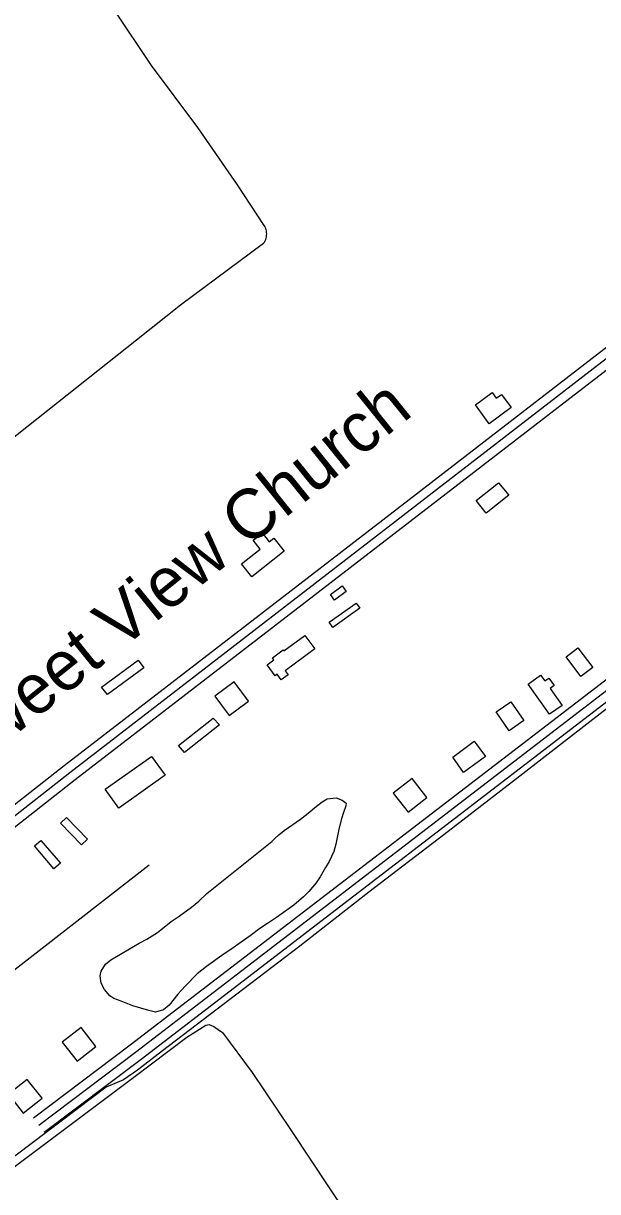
# Model space of a CAD drawing. Extents: x 3419139 to 3457078, y 540382 to 565875.
# Drawn here: x 3432771 to 3433728, y 559939 to 561886 of the extents above; entities that cross this region are included whole.
import ezdxf

# ---------------------------------------------------------------- set-up
doc = ezdxf.new("R2010")
doc.units = 0
for name, color, linetype in [('V-BLDG-OTLN', 7, 'Continuous'), ('V-DTCH-CNTR', 7, 'Continuous'), ('V-ROAD-CNTR', 7, 'Continuous'), ('V-SITE-OTLN-IDEN', 7, 'Continuous'), ('V-SITE-VEGE', 7, 'Continuous'), ('V-TOPO-SHOR', 7, 'Continuous')]:
    doc.layers.add(name, color=color, linetype=linetype)

msp = doc.modelspace()

# ---------------------------------------------------------------- linework, layer by layer
at = {"layer": 'V-BLDG-OTLN'}
for points in [[(3433584.154, 561245.871), (3433547.552, 561218.903), (3433524.438, 561250.268), (3433552.2830000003, 561270.783), (3433559.131, 561261.487), (3433567.694, 561267.799)], [(3433579.988, 561099.705), (3433542.452, 561069.8740000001), (3433525.88, 561090.727), (3433563.2090000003, 561120.392)], [(3433205.784, 561006.22), (3433151.835, 560963.794), (3433134.8510000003, 560985.388), (3433165.944, 561009.841), (3433154.365, 561024.562), (3433169.473, 561036.443), (3433180.708, 561022.156), (3433188.585, 561028.349)], [(3433282.9050000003, 560934.018), (3433302.646, 560948.434), (3433309.41, 560939.171), (3433289.461, 560924.601)], [(3433332.16, 560911.551), (3433286.768, 560879.214), (3433280.644, 560887.805), (3433325.7660000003, 560919.954)], [(3433256.9760000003, 560843.417), (3433207.6210000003, 560806.8910000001), (3433212.491, 560800.308), (3433200.985, 560791.795), (3433194.0470000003, 560801.172), (3433190.7, 560798.696), (3433177.378, 560816.7000000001), (3433188.857, 560825.196), (3433186.457, 560828.442), (3433204.434, 560841.745), (3433205.558, 560840.228), (3433240.032, 560865.738)], [(3433695.375, 560845.309), (3433720.051, 560812.402), (3433700.325, 560797.611), (3433675.685, 560830.469)], [(3432901.566, 560779.828), (3432962.404, 560824.618), (3432971.796, 560811.861), (3432911.271, 560767.305)], [(3433648.002, 560734.447), (3433612.1380000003, 560784.446), (3433633.199, 560799.555), (3433639.933, 560790.162), (3433646.544, 560794.904), (3433655.656, 560782.202), (3433649.034, 560777.453), (3433669.285, 560749.221)], [(3433122.410717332, 560788.4753966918), (3433090.4247813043, 560764.4574447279), (3433114.442733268, 560732.4715086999), (3433146.4296692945, 560756.4894606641)], [(3433583.406, 560755.154), (3433605.17, 560723.912), (3433580.934, 560707.028), (3433558.953, 560738.579)], [(3433097.858, 560716.6680000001), (3433039.574, 560670.473), (3433030.006, 560682.55), (3433087.311, 560727.9670000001)], [(3433486.73, 560662.849), (3433522.595, 560689.442), (3433541.222, 560664.323), (3433504.72, 560637.259)], [(3433007.802, 560632.745), (3432930.34, 560577.998), (3432907.849, 560609.822), (3432984.94, 560664.309)], [(3433412.282137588, 560571.325830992), (3433443.820074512, 560595.93178178), (3433419.214123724, 560627.4687187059), (3433387.6771867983, 560602.863767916)], [(3432843.175275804, 560562.4028488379), (3432877.9642062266, 560526.4899206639), (3432867.909226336, 560516.748940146), (3432833.119295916, 560552.6608683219)], [(3432800.6323608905, 560524.095925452), (3432832.96729622, 560485.9580017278), (3432822.2883175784, 560476.9050198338), (3432789.954382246, 560515.0419435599)], [(3432860.714240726, 560156.1116614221), (3432892.25217765, 560180.7176122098), (3432867.646226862, 560212.2545491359), (3432836.1092899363, 560187.649598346)], [(3432770.93742028, 560069.5838344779), (3432802.475357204, 560094.189785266), (3432777.869406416, 560125.7267221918), (3432746.33246949, 560101.1217714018)]]:
    msp.add_lwpolyline(points, close=True, dxfattribs=at)
at = {"layer": 'V-DTCH-CNTR'}
for points in [[(3433171.662, 561519.687), (3433172.997, 561521.706), (3433174.142, 561523.84), (3433175.09, 561526.066), (3433175.832, 561528.372), (3433176.358, 561530.736), (3433176.669, 561533.136), (3433176.762, 561535.557), (3433176.632, 561537.973), (3433176.284, 561540.3690000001), (3433175.719, 561542.723), (3433174.943, 561545.0160000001), (3433173.96, 561547.228), (3433172.7800000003, 561549.344), (3433171.412, 561551.343), (3433128.203, 561617.155), (3433062.2090000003, 561712.954), (3432984.8910000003, 561816.403), (3432923.051, 561908.684)], [(3432959.79, 561358.917), (3433033.303, 561417.3640000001), (3433171.662, 561519.687)], [(3431548.477, 560239.963), (3431799.103, 560438.21), (3432141.409, 560708.965), (3432223.418, 560774.215), (3432454.117, 560957.7710000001), (3432623.4, 561091.827), (3432796.028, 561228.533), (3432959.79, 561358.917)], [(3432084.883, 559782.073), (3432408.293, 560033.4450000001), (3432724.58, 560283.764), (3432981.151, 560483.481)], [(3432955.362, 560129.613), (3433043.412, 560196.093), (3433075.512, 560216.258), (3433080.913, 560217.169), (3433088.7120000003, 560214.13), (3433103.281, 560204.1460000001), (3433152.396, 560137.383), (3433217.293, 560040.535), (3433282.184, 559943.198), (3433332.178, 559868.585), (3433407.174, 559756.912), (3433465.2630000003, 559664.072), (3433493.376, 559626.468)], [(3431800.495, 559247.0700000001), (3432052.985, 559439.365), (3432407.205, 559714.246), (3432503.928, 559788.3910000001), (3432683.73, 559926.226), (3432955.362, 560129.613)]]:
    msp.add_lwpolyline(points, dxfattribs=at)
at = {"layer": 'V-ROAD-CNTR'}
for points in [[(3434797.202367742, 562157.2506591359), (3434727.801506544, 562110.8247519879), (3434368.383225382, 561829.81431401), (3434030.050902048, 561566.9498397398), (3433718.802524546, 561327.6783182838), (3433370.145221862, 561058.2678571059), (3432839.3752834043, 560648.59667645), (3432520.849920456, 560398.6491763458)], [(3434805.542351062, 562144.782684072), (3434736.6034889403, 562098.665776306), (3434377.60420694, 561817.983337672), (3434039.2238837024, 561555.080863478), (3433727.9595062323, 561315.797342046), (3433379.313203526, 561046.3958808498), (3432848.5882649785, 560636.758700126), (3432530.1099019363, 560386.8481999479)], [(3434813.8823343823, 562132.314709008), (3434745.4054713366, 562086.506800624), (3434386.825188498, 561806.1523613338), (3434048.3968653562, 561543.2118872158), (3433737.116487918, 561303.916365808), (3433388.4811851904, 561034.523904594), (3432857.8012465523, 560624.9207238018), (3432539.369883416, 560375.0472235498)], [(3434929.83310248, 561716.8495399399), (3434860.5892409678, 561670.701632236), (3434483.716994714, 561368.14523735), (3433834.974292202, 560863.2962470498), (3432949.28706358, 560182.6376083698), (3432788.1243859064, 560060.976851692)], [(3434938.152085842, 561704.367564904), (3434869.461223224, 561658.5886564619), (3434493.01897611, 561356.377260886), (3433844.15027385, 560851.430270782), (3432958.376045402, 560170.704632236), (3432797.161367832, 560049.0048756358)], [(3434946.4710692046, 561691.8855898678), (3434878.33320548, 561646.4756806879), (3434502.320957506, 561344.6092844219), (3433853.326255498, 560839.5642945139), (3432967.4650272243, 560158.7716561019), (3432806.198349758, 560037.03289958)]]:
    msp.add_lwpolyline(points, dxfattribs=at)
at = {"layer": 'V-SITE-VEGE'}
msp.add_lwpolyline([(3433085.46, 560442.117), (3433185.443, 560522.216), (3433190.231, 560527.541), (3433197.199, 560533.55), (3433205.989, 560540.607), (3433233.041, 560559.603), (3433248.417, 560571.5920000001), (3433256.853, 560579.0160000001), (3433268.936, 560588.541), (3433277.685, 560593.434), (3433292.517, 560595.328), (3433302.552, 560591.535), (3433308.954, 560586.368), (3433308.5130000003, 560582.045), (3433304.702, 560570.926), (3433301.622, 560560.156), (3433296.973, 560542.9180000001), (3433291.822, 560517.75), (3433288.353, 560505.544), (3433280.829, 560488.719), (3433274.873, 560478.721), (3433265.929, 560463.367), (3433259.253, 560453.383), (3433247.078, 560438.81), (3433237.892, 560429.954), (3433221.762, 560416.1730000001), (3433193.236, 560395.402), (3433179.7290000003, 560386.987), (3433165.475, 560377.142), (3433149.015, 560365.17), (3433120.861, 560345.116), (3433102.22, 560332.103), (3433076.623, 560313.804), (3433060.8880000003, 560301.819), (3433040.664, 560281.255), (3433028.509, 560267.765), (3433014.103, 560249.622), (3433004.572, 560241.495), (3432991.512, 560237.764), (3432980.375, 560240.4940000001), (3432953.8140000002, 560248.557), (3432934.1040000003, 560256.132), (3432921.917, 560260.687), (3432915.136, 560264.781), (3432906.313, 560275.7660000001), (3432900.7260000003, 560285.974), (3432899.151, 560298.634), (3432901.095, 560306.177), (3432908.164, 560317.957), (3432916.954, 560325.015), (3432945.411, 560341.818), (3432964.0130000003, 560352.667), (3432976.772, 560359.652), (3432994.662, 560370.873), (3433000.5130000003, 560375.098), (3433017.724, 560388.859), (3433030.882, 560398.001), (3433051.362, 560412.786), (3433063.812, 560422.6630000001), (3433077.036, 560435.414)], close=True, dxfattribs=at)
at = {"layer": 'V-TOPO-SHOR'}
for points in [[(3434649.6950000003, 561445.49), (3434561.177, 561377.578), (3434461.29, 561301.487), (3434344.5640000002, 561210.43), (3434235.289, 561127.603), (3434123.99, 561039.906), (3434026.057, 560963.3), (3433904.41, 560870.35), (3433811.404, 560796.128), (3433710.024, 560718.0970000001), (3433598.25, 560631.385), (3433471.645, 560533.601), (3433347.022, 560437.7490000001), (3433231.7770000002, 560347.653), (3433115.0840000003, 560259.046), (3433003.3200000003, 560173.313), (3432961.287, 560141.0430000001), (3432938.063, 560124.691), (3432909.02, 560112.819)], [(3432909.02, 560112.819), (3432736.646, 559982.231), (3432450.727, 559761.309), (3432107.843, 559495.417), (3431783.046, 559242.546), (3431675.954, 559159.408), (3431443.455, 558981.567), (3431145.332, 558754.2390000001), (3430815.835, 558495.512), (3430510.077, 558255.846), (3430333.363, 558112.9450000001), (3430254.042, 558048.804), (3430078.056, 557912.432)]]:
    msp.add_lwpolyline(points, dxfattribs=at)

# ---------------------------------------------------------------- texts
at = {"layer": 'V-SITE-OTLN-IDEN'}
msp.add_text('Sweet View Church', height=82.999832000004, rotation=38.84723978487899, dxfattribs=at).set_placement((3432668.438758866, 560627.3236259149))

doc.saveas('drawing.dxf')
